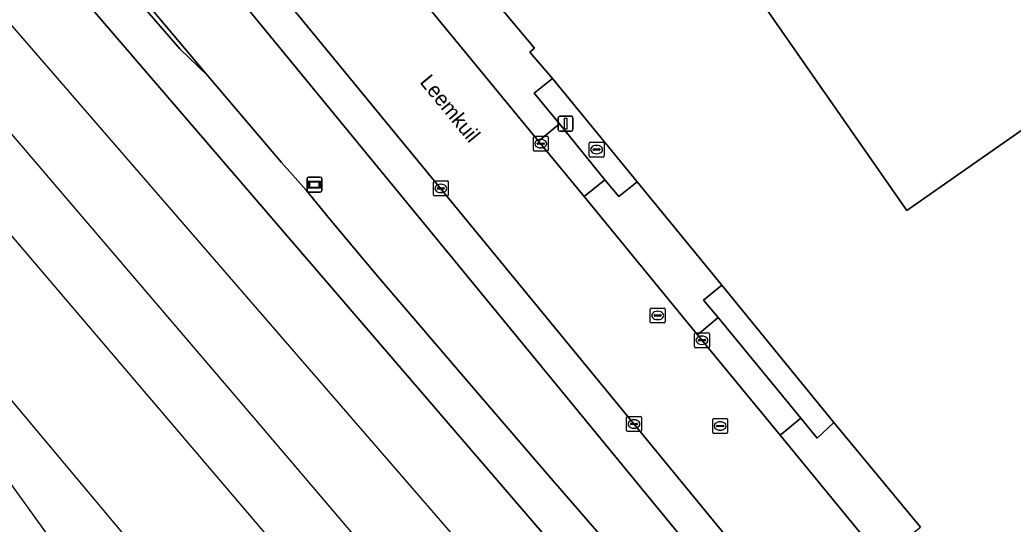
# Model space of a CAD drawing. Extents: x 156702 to 158052, y 387630 to 388992.
# Drawn here: x 156998.2 to 157065, y 388017.6 to 388051.5 of the extents above; entities that cross this region are included whole.
import ezdxf

# ---------------------------------------------------------------- set-up
doc = ezdxf.new("R2010")
doc.units = 0
for name, color, linetype in [('IMGEO_Berm_groen', 7, 'Continuous'), ('IMGEO_Brandkraan', 7, 'Continuous'), ('IMGEO_Erf', 7, 'Continuous'), ('IMGEO_Grasland_overig', 7, 'Continuous'), ('IMGEO_Groenvoorziening', 7, 'Continuous'), ('IMGEO_Kolk', 7, 'Continuous'), ('IMGEO_Lichtmast', 7, 'Continuous'), ('IMGEO_Muur', 7, 'Continuous'), ('IMGEO_Openbare_ruimte_label', 7, 'Continuous'), ('IMGEO_Pand', 7, 'Continuous'), ('IMGEO_Parkeervlak_open', 7, 'Continuous'), ('IMGEO_Rijbaan_lokaal_gesloten', 7, 'Continuous'), ('IMGEO_Rioolput', 7, 'Continuous'), ('IMGEO_Spoor', 7, 'Continuous'), ('IMGEO_Spoorbaan_halfverhard', 7, 'Continuous'), ('IMGEO_Verklikker', 7, 'Continuous'), ('IMGEO_Voetpad_open', 7, 'Continuous')]:
    doc.layers.add(name, color=color, linetype=linetype)

msp = doc.modelspace()

# ---------------------------------------------------------------- linework, layer by layer
at = {"layer": 'IMGEO_Berm_groen'}
for points in [[(157082.395, 387968.454), (157010.543, 388055.913), (156935.425, 388147.089)], [(156944.225, 388126.72), (156950.711, 388119.018), (156952.34, 388117.123), (156958.864, 388109.39), (156962.089, 388105.53), (157002.807, 388057.385), (157007.62, 388051.585), (157010.871, 388047.739), (157015.806, 388041.931), (157017.476, 388040.057), (157019.054, 388038.118), (157022.285, 388034.28), (157028.842, 388026.615), (157033.784, 388020.889), (157037.446, 388016.646)]]:
    msp.add_lwpolyline(points, dxfattribs=at)
at = {"layer": 'IMGEO_Brandkraan'}
for p, q in [((157036.486, 388042.368), (157036.486, 388043.22)), ((157036.561, 388043.294), (157037.413, 388043.294)), ((157036.745, 388042.788), (157036.745, 388042.8)), ((157037.183, 388042.751), (157036.785, 388042.751)), ((157036.788, 388042.837), (157037.186, 388042.837)), ((157036.974, 388043.074), (157036.999, 388043.074)), ((157037.229, 388042.8), (157037.229, 388042.788)), ((157037.487, 388043.22), (157037.487, 388042.368)), ((157037.413, 388042.294), (157036.561, 388042.294)), ((157036.997, 388042.514), (157036.972, 388042.514))]:
    msp.add_line(p, q, dxfattribs=at)
for points in [[(157036.486, 388042.368), (157036.486, 388043.22)], [(157036.561, 388043.294), (157037.413, 388043.294)], [(157037.487, 388043.22), (157037.487, 388042.368)], [(157037.413, 388042.294), (157036.561, 388042.294)]]:
    msp.add_lwpolyline(points, dxfattribs=at)
for centre, radius, start, end in [((157036.563, 388043.218), 0.0765, 91.55205, 178.44795), ((157036.563, 388043.218), 0.0765, 91.55205, 178.44795), ((157036.785, 388042.797), 0.0403, 85.87752, 175.75265), ((157036.782, 388042.787), 0.0366, 178.93798, 274.71019), ((157037.186, 388042.794), 0.043, 264.86636, 352.45326), ((157037.19, 388042.799), 0.0386, 1.73085, 96.63898), ((157037.411, 388043.218), 0.0765, 1.55205, 88.44795), ((157037.411, 388043.218), 0.0765, 1.55205, 88.44795), ((157036.563, 388042.37), 0.0765, 181.55205, 268.44795), ((157036.563, 388042.37), 0.0765, 181.55205, 268.44795), ((157037.411, 388042.37), 0.0765, 271.55205, 358.44795), ((157037.411, 388042.37), 0.0765, 271.55205, 358.44795)]:
    msp.add_arc(centre, radius, start, end, dxfattribs=at)
for centre, major_axis, ratio, start_param, end_param in [((157036.973, 388042.794), (-0.387, 0.002), 0.722429, 4.712389, 7.853982), ((157036.998, 388042.794), (-0.39, 0.002), 0.717154, 1.570796, 4.712389)]:
    msp.add_ellipse(centre, major_axis=major_axis, ratio=ratio, start_param=start_param, end_param=end_param, dxfattribs=at)
at = {"layer": 'IMGEO_Erf'}
msp.add_lwpolyline([(157105.652, 388146.193), (157140.444, 388096.391), (157061.943, 388041.565), (157057.843, 388038.702), (157040.372, 388063.762), (157036.435, 388065.83), (157037.502, 388067.883), (157033.567, 388069.945), (157034.64, 388071.979), (157033.675, 388073.418), (157031.286, 388071.77), (157023.075, 388083.589), (157022.6, 388083.259), (157022.377, 388083.628), (157022.852, 388083.953), (157021.07, 388086.552), (157020.607, 388086.255), (157020.351, 388086.577), (157020.768, 388086.889), (157016.648, 388092.763), (157020.743, 388095.634), (157027.334, 388100.255), (157031.446, 388094.362)], close=True, dxfattribs=at)
msp.add_lwpolyline([(156968.59, 388127.099), (156969.571, 388125.885), (156969.838, 388126.064), (156973.576, 388121.584), (156973.316, 388121.36), (156974.286, 388120.211), (156992.542, 388098.374), (156998.5, 388091.135), (156998.304, 388090.944), (156999.905, 388089.048), (156999.986, 388089.107), (157002.994, 388085.513), (157002.903, 388085.425), (157003.851, 388084.28), (157025.194, 388058.307), (157026.563, 388056.715), (157026.735, 388056.888), (157032.812, 388049.597), (157032.495, 388049.328), (157034.035, 388047.576), (157039.706, 388040.637), (157045.394, 388033.689), (157052.929, 388024.461), (157058.764, 388017.433)], dxfattribs=at)
at = {"layer": 'IMGEO_Grasland_overig'}
for points in [[(156929.103, 388138.77), (156962.414, 388099.504), (157042.808, 388006.065), (157068.122, 387976.848), (157123.947, 387911.695), (157157.305, 387872.588)], [(156942.697, 388126.718), (156967.711, 388097.26), (156995.6, 388064.978), (157008.978, 388049.557), (157010.871, 388047.739), (157007.62, 388051.585), (157002.807, 388057.385), (156962.089, 388105.53), (156958.864, 388109.39), (156952.34, 388117.123), (156950.711, 388119.018), (156944.225, 388126.72)], [(157037.446, 388016.646), (157033.784, 388020.889), (157028.842, 388026.615), (157022.285, 388034.28), (157019.054, 388038.118), (157017.476, 388040.057), (157015.806, 388041.931), (157010.871, 388047.739), (157008.978, 388049.557), (156995.6, 388064.978), (156967.711, 388097.26), (156942.697, 388126.718)]]:
    msp.add_lwpolyline(points, dxfattribs=at)
at = {"layer": 'IMGEO_Groenvoorziening'}
for points in [[(157039.706, 388040.637), (157034.035, 388047.576), (157032.796, 388046.58), (157034.486, 388044.512), (157037.542, 388040.762), (157038.487, 388039.641)], [(157052.929, 388024.461), (157045.394, 388033.689), (157044.178, 388032.683), (157045.163, 388031.519), (157050.705, 388024.762), (157051.812, 388023.425)]]:
    msp.add_lwpolyline(points, close=True, dxfattribs=at)
at = {"layer": 'IMGEO_Kolk'}
for p, q in [((157032.738, 388042.764), (157032.738, 388043.616)), ((157032.813, 388043.69), (157033.665, 388043.69)), ((157033.226, 388043.47), (157033.251, 388043.47)), ((157033.739, 388043.616), (157033.739, 388042.764)), ((157033.665, 388042.69), (157032.813, 388042.69)), ((157032.997, 388043.184), (157032.997, 388043.196)), ((157033.435, 388043.147), (157033.037, 388043.147)), ((157033.04, 388043.233), (157033.438, 388043.233)), ((157033.249, 388042.91), (157033.224, 388042.91)), ((157033.481, 388043.196), (157033.481, 388043.184)), ((157026.1, 388040.685), (157026.952, 388040.685)), ((157026.025, 388039.759), (157026.025, 388040.611)), ((157026.284, 388040.179), (157026.284, 388040.191)), ((157026.722, 388040.142), (157026.324, 388040.142)), ((157026.327, 388040.228), (157026.725, 388040.228)), ((157026.513, 388040.465), (157026.538, 388040.465)), ((157026.768, 388040.191), (157026.768, 388040.179)), ((157027.026, 388040.611), (157027.026, 388039.759)), ((157026.952, 388039.685), (157026.1, 388039.685)), ((157026.536, 388039.905), (157026.511, 388039.905)), ((157043.568, 388029.562), (157043.568, 388030.414)), ((157043.643, 388030.488), (157044.495, 388030.488)), ((157043.827, 388029.982), (157043.827, 388029.994)), ((157043.87, 388030.031), (157044.268, 388030.031)), ((157044.056, 388030.268), (157044.081, 388030.268)), ((157044.311, 388029.994), (157044.311, 388029.982)), ((157044.569, 388030.414), (157044.569, 388029.562)), ((157044.495, 388029.488), (157043.643, 388029.488)), ((157044.265, 388029.945), (157043.867, 388029.945)), ((157044.079, 388029.708), (157044.054, 388029.708)), ((157039, 388023.94), (157039, 388024.792)), ((157039.075, 388024.866), (157039.927, 388024.866)), ((157040.001, 388024.792), (157040.001, 388023.94)), ((157039.259, 388024.36), (157039.259, 388024.372)), ((157039.697, 388024.323), (157039.299, 388024.323)), ((157039.302, 388024.409), (157039.7, 388024.409)), ((157039.511, 388024.086), (157039.486, 388024.086)), ((157039.488, 388024.646), (157039.513, 388024.646)), ((157039.743, 388024.372), (157039.743, 388024.36)), ((157039.927, 388023.866), (157039.075, 388023.866))]:
    msp.add_line(p, q, dxfattribs=at)
for points in [[(157032.738, 388042.764), (157032.738, 388043.616)], [(157032.813, 388043.69), (157033.665, 388043.69)], [(157033.739, 388043.616), (157033.739, 388042.764)], [(157033.665, 388042.69), (157032.813, 388042.69)], [(157026.1, 388040.685), (157026.952, 388040.685)], [(157026.025, 388039.759), (157026.025, 388040.611)], [(157027.026, 388040.611), (157027.026, 388039.759)], [(157026.952, 388039.685), (157026.1, 388039.685)], [(157043.568, 388029.562), (157043.568, 388030.414)], [(157043.643, 388030.488), (157044.495, 388030.488)], [(157044.569, 388030.414), (157044.569, 388029.562)], [(157044.495, 388029.488), (157043.643, 388029.488)], [(157039, 388023.94), (157039, 388024.792)], [(157039.075, 388024.866), (157039.927, 388024.866)], [(157040.001, 388024.792), (157040.001, 388023.94)], [(157039.927, 388023.866), (157039.075, 388023.866)]]:
    msp.add_lwpolyline(points, dxfattribs=at)
for centre, radius, start, end in [((157032.815, 388043.614), 0.0765, 91.55205, 178.44795), ((157032.815, 388043.614), 0.0765, 91.55205, 178.44795), ((157033.663, 388043.614), 0.0765, 1.55205, 88.44795), ((157033.663, 388043.614), 0.0765, 1.55205, 88.44795), ((157032.815, 388042.766), 0.0765, 181.55205, 268.44795), ((157032.815, 388042.766), 0.0765, 181.55205, 268.44795), ((157033.037, 388043.193), 0.0403, 85.87752, 175.75265), ((157033.034, 388043.183), 0.0366, 178.93798, 274.71019), ((157033.438, 388043.19), 0.043, 264.86636, 352.45326), ((157033.442, 388043.195), 0.0386, 1.73085, 96.63898), ((157033.663, 388042.766), 0.0765, 271.55205, 358.44795), ((157033.663, 388042.766), 0.0765, 271.55205, 358.44795), ((157026.102, 388040.609), 0.0765, 91.55205, 178.44795), ((157026.102, 388040.609), 0.0765, 91.55205, 178.44795), ((157026.95, 388040.609), 0.0765, 1.55205, 88.44795), ((157026.95, 388040.609), 0.0765, 1.55205, 88.44795), ((157026.324, 388040.188), 0.0403, 85.87752, 175.75265), ((157026.321, 388040.178), 0.0366, 178.93798, 274.71019), ((157026.725, 388040.185), 0.043, 264.86636, 352.45326), ((157026.729, 388040.19), 0.0386, 1.73085, 96.63898), ((157026.102, 388039.761), 0.0765, 181.55205, 268.44795), ((157026.102, 388039.761), 0.0765, 181.55205, 268.44795), ((157026.95, 388039.761), 0.0765, 271.55205, 358.44795), ((157026.95, 388039.761), 0.0765, 271.55205, 358.44795), ((157043.645, 388030.412), 0.0765, 91.55205, 178.44795), ((157043.645, 388030.412), 0.0765, 91.55205, 178.44795), ((157043.867, 388029.991), 0.0403, 85.87752, 175.75265), ((157044.272, 388029.993), 0.0386, 1.73085, 96.63898), ((157044.493, 388030.412), 0.0765, 1.55205, 88.44795), ((157044.493, 388030.412), 0.0765, 1.55205, 88.44795), ((157043.645, 388029.564), 0.0765, 181.55205, 268.44795), ((157043.645, 388029.564), 0.0765, 181.55205, 268.44795), ((157043.864, 388029.981), 0.0366, 178.93798, 274.71019), ((157044.268, 388029.988), 0.043, 264.86636, 352.45326), ((157044.493, 388029.564), 0.0765, 271.55205, 358.44795), ((157044.493, 388029.564), 0.0765, 271.55205, 358.44795), ((157039.077, 388024.79), 0.0765, 91.55205, 178.44795), ((157039.077, 388024.79), 0.0765, 91.55205, 178.44795), ((157039.925, 388024.79), 0.0765, 1.55205, 88.44795), ((157039.925, 388024.79), 0.0765, 1.55205, 88.44795), ((157039.299, 388024.369), 0.0403, 85.87752, 175.75265), ((157039.296, 388024.359), 0.0366, 178.93798, 274.71019), ((157039.7, 388024.366), 0.043, 264.86636, 352.45326), ((157039.704, 388024.371), 0.0386, 1.73085, 96.63898), ((157039.077, 388023.942), 0.0765, 181.55205, 268.44795), ((157039.077, 388023.942), 0.0765, 181.55205, 268.44795), ((157039.925, 388023.942), 0.0765, 271.55205, 358.44795), ((157039.925, 388023.942), 0.0765, 271.55205, 358.44795)]:
    msp.add_arc(centre, radius, start, end, dxfattribs=at)
for centre, major_axis, ratio, start_param, end_param in [((157033.225, 388043.19), (-0.387, 0.002), 0.722429, 4.712389, 7.853982), ((157033.25, 388043.19), (-0.39, 0.002), 0.717154, 1.570796, 4.712389), ((157026.512, 388040.185), (-0.387, 0.002), 0.722429, 4.712389, 7.853982), ((157026.537, 388040.185), (-0.39, 0.002), 0.717154, 1.570796, 4.712389), ((157044.055, 388029.988), (-0.387, 0.002), 0.722429, 4.712389, 7.853982), ((157044.08, 388029.988), (-0.39, 0.002), 0.717154, 1.570796, 4.712389), ((157039.487, 388024.366), (-0.387, 0.002), 0.722429, 4.712389, 7.853982), ((157039.512, 388024.366), (-0.39, 0.002), 0.717154, 1.570796, 4.712389)]:
    msp.add_ellipse(centre, major_axis=major_axis, ratio=ratio, start_param=start_param, end_param=end_param, dxfattribs=at)
at = {"layer": 'IMGEO_Lichtmast'}
for p, q in [((157034.408, 388044.131), (157034.408, 388044.931)), ((157034.408, 388044.931), (157034.408, 388044.131)), ((157034.508, 388045.031), (157035.298, 388045.031)), ((157035.298, 388045.031), (157034.508, 388045.031)), ((157035.398, 388044.931), (157035.398, 388044.131)), ((157035.398, 388044.131), (157035.398, 388044.931)), ((157035.298, 388044.031), (157034.508, 388044.031)), ((157034.508, 388044.031), (157035.298, 388044.031))]:
    msp.add_line(p, q, dxfattribs=at)
msp.add_lwpolyline([(157034.828, 388044.906), (157034.978, 388044.906), (157034.978, 388044.156), (157034.828, 388044.156), (157034.828, 388044.906)], dxfattribs=at)
for centre, start, end in [((157034.508, 388044.931), 90, 180), ((157034.508, 388044.931), 90, 180), ((157035.298, 388044.931), 0, 90), ((157035.298, 388044.931), 360, 90), ((157034.508, 388044.131), 180, 270), ((157034.508, 388044.131), 180, 270), ((157035.298, 388044.131), 270, 0), ((157035.298, 388044.131), 270, 0)]:
    msp.add_arc(centre, 0.1, start, end, dxfattribs=at)
at = {"layer": 'IMGEO_Muur'}
for points in [[(156944.225, 388126.72), (156950.711, 388119.018), (156952.34, 388117.123), (156958.864, 388109.39), (156962.089, 388105.53), (157002.807, 388057.385), (157007.62, 388051.585), (157010.871, 388047.739), (157015.806, 388041.931), (157017.476, 388040.057), (157019.054, 388038.118), (157022.285, 388034.28), (157028.842, 388026.615)], [(157028.842, 388026.615), (157033.784, 388020.889), (157037.446, 388016.646), (157051.628, 388000.142)]]:
    msp.add_lwpolyline(points, dxfattribs=at)
at = {"layer": 'IMGEO_Pand'}
msp.add_lwpolyline([(157057.843, 388038.702), (157061.943, 388041.565), (157140.444, 388096.391), (157105.652, 388146.193), (157031.446, 388094.362), (157027.334, 388100.255), (157020.743, 388095.634), (157016.648, 388092.763), (157020.768, 388086.889), (157020.351, 388086.577), (157020.607, 388086.255), (157021.07, 388086.552), (157022.852, 388083.953), (157022.377, 388083.628), (157022.6, 388083.259), (157023.075, 388083.589), (157031.286, 388071.77), (157033.675, 388073.418), (157034.64, 388071.979), (157033.567, 388069.945), (157037.502, 388067.883), (157036.435, 388065.83), (157040.372, 388063.762)], close=True, dxfattribs=at)
at = {"layer": 'IMGEO_Parkeervlak_open'}
for points in [[(156935.425, 388147.089), (157010.543, 388055.913), (157082.395, 387968.454)], [(157086.65, 387967.254), (157076.143, 387979.783), (156975.736, 388101.937)]]:
    msp.add_lwpolyline(points, dxfattribs=at)
at = {"layer": 'IMGEO_Rijbaan_lokaal_gesloten'}
for points in [[(156949.39, 388133.888), (156975.736, 388101.937), (157076.143, 387979.783), (157086.65, 387967.254), (157168.303, 387867.992)], [(157151.823, 387898.922), (157135.296, 387919), (157127.008, 387929.069), (157119.374, 387938.343), (157108.17, 387951.954), (157107.707, 387952.557), (157107.168, 387953.161), (157106.681, 387953.807), (157090.708, 387973.286), (157057.178, 388014.032), (157049.316, 388023.624), (157043.772, 388030.36), (157036.155, 388039.64), (157033.095, 388043.357), (157021.524, 388057.416), (157003.194, 388079.652), (156988.601, 388097.391), (156973.268, 388116.017), (156964.812, 388126.277)]]:
    msp.add_lwpolyline(points, dxfattribs=at)
at = {"layer": 'IMGEO_Rioolput'}
for p, q in [((157040.594, 388031.227), (157040.594, 388032.079)), ((157040.669, 388032.153), (157041.521, 388032.153)), ((157041.595, 388032.079), (157041.595, 388031.227)), ((157040.853, 388031.647), (157040.853, 388031.659)), ((157041.291, 388031.61), (157040.893, 388031.61)), ((157040.896, 388031.696), (157041.294, 388031.696)), ((157041.105, 388031.373), (157041.08, 388031.373)), ((157041.082, 388031.933), (157041.107, 388031.933)), ((157041.337, 388031.659), (157041.337, 388031.647)), ((157041.521, 388031.153), (157040.669, 388031.153)), ((157044.792, 388023.805), (157044.792, 388024.657)), ((157044.867, 388024.731), (157045.719, 388024.731)), ((157045.793, 388024.657), (157045.793, 388023.805)), ((157045.051, 388024.225), (157045.051, 388024.237)), ((157045.489, 388024.188), (157045.091, 388024.188)), ((157045.094, 388024.274), (157045.492, 388024.274)), ((157045.28, 388024.511), (157045.305, 388024.511)), ((157045.535, 388024.237), (157045.535, 388024.225)), ((157045.719, 388023.731), (157044.867, 388023.731)), ((157045.303, 388023.951), (157045.278, 388023.951))]:
    msp.add_line(p, q, dxfattribs=at)
for points in [[(157040.594, 388031.227), (157040.594, 388032.079)], [(157040.669, 388032.153), (157041.521, 388032.153)], [(157041.595, 388032.079), (157041.595, 388031.227)], [(157041.521, 388031.153), (157040.669, 388031.153)], [(157044.792, 388023.805), (157044.792, 388024.657)], [(157044.867, 388024.731), (157045.719, 388024.731)], [(157045.793, 388024.657), (157045.793, 388023.805)], [(157045.719, 388023.731), (157044.867, 388023.731)]]:
    msp.add_lwpolyline(points, dxfattribs=at)
for centre, radius, start, end in [((157040.671, 388032.077), 0.0765, 91.55205, 178.44795), ((157040.671, 388032.077), 0.0765, 91.55205, 178.44795), ((157041.519, 388032.077), 0.0765, 1.55205, 88.44795), ((157041.519, 388032.077), 0.0765, 1.55205, 88.44795), ((157040.893, 388031.656), 0.0403, 85.87752, 175.75265), ((157040.89, 388031.646), 0.0366, 178.93798, 274.71019), ((157041.294, 388031.653), 0.043, 264.86636, 352.45326), ((157041.298, 388031.658), 0.0386, 1.73085, 96.63898), ((157040.671, 388031.229), 0.0765, 181.55205, 268.44795), ((157040.671, 388031.229), 0.0765, 181.55205, 268.44795), ((157041.519, 388031.229), 0.0765, 271.55205, 358.44795), ((157041.519, 388031.229), 0.0765, 271.55205, 358.44795), ((157044.869, 388024.655), 0.0765, 91.55205, 178.44795), ((157044.869, 388024.655), 0.0765, 91.55205, 178.44795), ((157045.717, 388024.655), 0.0765, 1.55205, 88.44795), ((157045.717, 388024.655), 0.0765, 1.55205, 88.44795), ((157045.091, 388024.234), 0.0403, 85.87752, 175.75265), ((157045.088, 388024.224), 0.0366, 178.93798, 274.71019), ((157045.492, 388024.231), 0.043, 264.86636, 352.45326), ((157045.496, 388024.236), 0.0386, 1.73085, 96.63898), ((157044.869, 388023.807), 0.0765, 181.55205, 268.44795), ((157044.869, 388023.807), 0.0765, 181.55205, 268.44795), ((157045.717, 388023.807), 0.0765, 271.55205, 358.44795), ((157045.717, 388023.807), 0.0765, 271.55205, 358.44795)]:
    msp.add_arc(centre, radius, start, end, dxfattribs=at)
for centre, major_axis, ratio, start_param, end_param in [((157041.081, 388031.653), (-0.387, 0.002), 0.722429, 4.712389, 7.853982), ((157041.106, 388031.653), (-0.39, 0.002), 0.717154, 1.570796, 4.712389), ((157045.279, 388024.231), (-0.387, 0.002), 0.722429, 4.712389, 7.853982), ((157045.304, 388024.231), (-0.39, 0.002), 0.717154, 1.570796, 4.712389)]:
    msp.add_ellipse(centre, major_axis=major_axis, ratio=ratio, start_param=start_param, end_param=end_param, dxfattribs=at)
at = {"layer": 'IMGEO_Spoor'}
for points in [[(156872.422, 388201.343), (156882.919, 388187.987), (156900.381, 388166.18), (156921.457, 388140.635), (156943.252, 388114.607), (156960.211, 388094.663), (156986.26, 388064.316), (157082.584, 387953.12), (157127.585, 387900.649), (157147.691, 387876.906), (157152.061, 387871.615)], [(156869.112, 388198.606), (156881.132, 388183.363), (156896.988, 388163.695), (156934.031, 388118.813), (156947.895, 388102.263), (156968.651, 388077.779), (157013.933, 388024.808), (157050.907, 387981.407), (157095.657, 387928.292), (157129.461, 387887.97), (157178.378, 387828.835), (157215.755, 387783.487)], [(156865.308, 388195.462), (156870.022, 388189.509), (156887.814, 388167.443), (156909.51, 388141.178), (156951.276, 388091.519), (156994.8, 388040.336), (157047.715, 387978.302), (157077.25, 387943.427), (157106.481, 387908.588), (157145.615, 387861.584), (157233.331, 387755.475), (157295.4, 387680.676)], [(156861.38, 388192.215), (156889.992, 388156.032), (156904.613, 388138.066), (156936.994, 388098.664), (156975.894, 388051.914), (157129.969, 387867.975), (157185.575, 387801.306), (157243.801, 387730.926), (157317.91, 387641.153), (157319.189, 387639.479), (157324.467, 387633.086)]]:
    msp.add_lwpolyline(points, dxfattribs=at)
at = {"layer": 'IMGEO_Spoorbaan_halfverhard'}
for points in [[(157157.305, 387872.588), (157123.947, 387911.695), (157068.122, 387976.848), (157042.808, 388006.065), (156962.414, 388099.504), (156929.103, 388138.77)], [(156908.584, 388126.427), (156918.87, 388113.037), (156922.702, 388111.082), (156941.441, 388086.192), (156941.899, 388085.652), (156945.056, 388081.855), (156959.9, 388067.651), (156991.384, 388028.983), (157011.619, 388000.866), (157063.394, 387938.926), (157175.065, 387804.02)]]:
    msp.add_lwpolyline(points, dxfattribs=at)
at = {"layer": 'IMGEO_Verklikker'}
for p, q in [((157017.532, 388040.042), (157017.532, 388040.842)), ((157017.532, 388040.842), (157017.532, 388040.042)), ((157017.632, 388040.942), (157018.422, 388040.942)), ((157018.422, 388040.942), (157017.632, 388040.942)), ((157018.522, 388040.842), (157018.522, 388040.042)), ((157018.522, 388040.042), (157018.522, 388040.842)), ((157018.422, 388039.942), (157017.632, 388039.942)), ((157017.632, 388039.942), (157018.422, 388039.942))]:
    msp.add_line(p, q, dxfattribs=at)
for points in [[(157017.633, 388040.674), (157018.421, 388040.674), (157018.421, 388040.21), (157017.633, 388040.21), (157017.633, 388040.674)], [(157017.698, 388040.609), (157017.698, 388040.275), (157018.356, 388040.275), (157018.356, 388040.609), (157017.698, 388040.609)]]:
    msp.add_lwpolyline(points, dxfattribs=at)
for centre, start, end in [((157017.632, 388040.842), 90, 180), ((157017.632, 388040.842), 90, 180), ((157018.422, 388040.842), 0, 90), ((157018.422, 388040.842), 360, 90), ((157017.632, 388040.042), 180, 270), ((157017.632, 388040.042), 180, 270), ((157018.422, 388040.042), 270, 0), ((157018.422, 388040.042), 270, 0)]:
    msp.add_arc(centre, 0.1, start, end, dxfattribs=at)
at = {"layer": 'IMGEO_Voetpad_open'}
for points in [[(157033.095, 388043.357), (157034.486, 388044.512), (157032.796, 388046.58), (157034.035, 388047.576), (157032.495, 388049.328), (157032.812, 388049.597), (157026.735, 388056.888), (157026.563, 388056.715), (157025.194, 388058.307), (157023.96, 388057.324), (157022.91, 388058.585), (157021.524, 388057.416)], [(157033.095, 388043.357), (157036.155, 388039.64), (157037.542, 388040.762), (157034.486, 388044.512)], [(157043.772, 388030.36), (157045.163, 388031.519), (157044.178, 388032.683), (157045.394, 388033.689), (157039.706, 388040.637), (157038.487, 388039.641), (157037.542, 388040.762), (157036.155, 388039.64)], [(157043.772, 388030.36), (157049.316, 388023.624), (157050.705, 388024.762), (157045.163, 388031.519)], [(157057.178, 388014.032), (157058.612, 388015.167), (157057.524, 388016.474), (157058.764, 388017.433), (157052.929, 388024.461), (157051.812, 388023.425), (157050.705, 388024.762), (157049.316, 388023.624)]]:
    msp.add_lwpolyline(points, close=True, dxfattribs=at)

# ---------------------------------------------------------------- texts
at = {"layer": 'IMGEO_Openbare_ruimte_label'}
msp.add_text('Leemkuil', height=1, rotation=309.43862, dxfattribs=at).set_placement((157025.06, 388047.309))

doc.saveas('drawing.dxf')
